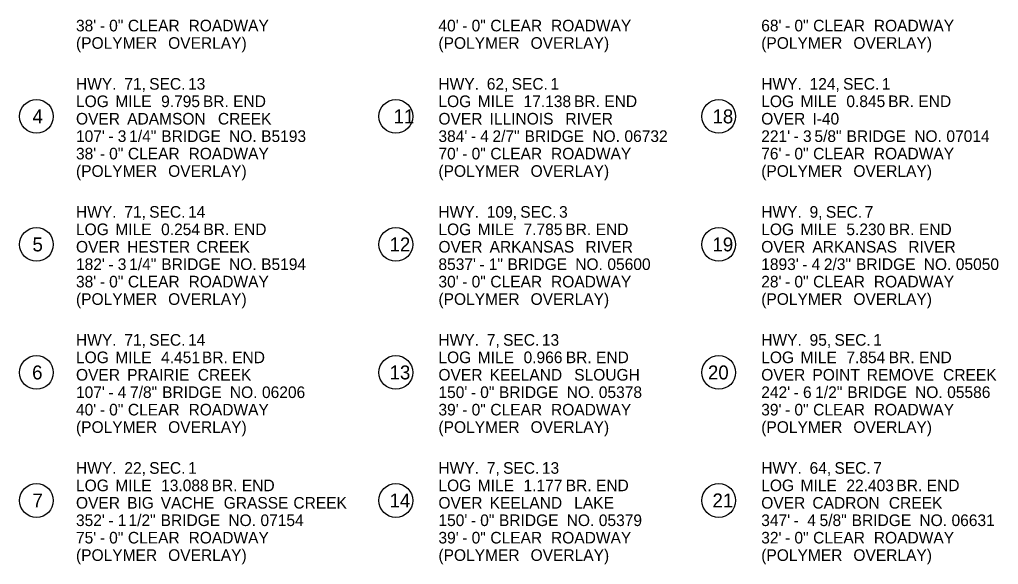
# Model space of a CAD drawing. Extents: x 1930546 to 1934225, y 596452 to 599553.
# Drawn here: x 1930658 to 1931501, y 598571 to 599039 of the extents above; entities that cross this region are included whole.
import ezdxf

# ---------------------------------------------------------------- set-up
doc = ezdxf.new("R2010")
doc.units = 0
doc.layers.add('Default', color=7, linetype='Continuous')
doc.layers.add('R_Border', color=7, linetype='Continuous')

msp = doc.modelspace()

# ---------------------------------------------------------------- linework, layer by layer
at = {"layer": 'R_Border'}
for centre in [(1930672.53, 598956.18), (1930981.88, 598956.18), (1931259.86, 598956.18), (1930672.53, 598846.01), (1930981.88, 598846.01), (1931259.86, 598846.01), (1930672.53, 598735.83), (1930981.88, 598735.83), (1931259.86, 598735.83), (1930672.53, 598625.66), (1930981.88, 598625.66), (1931259.86, 598625.66)]:
    msp.add_circle(centre, 14.52, dxfattribs=at)

# ---------------------------------------------------------------- texts
at = {"layer": 'Default'}
for s, p in [("38'", (1930706.56, 599029.34)), (' 0"', (1930731.4, 599029.34)), (' CLEAR', (1930747.53, 599029.34)), (' ROADWAY', (1930799.75, 599029.34)), ("40'", (1931018.56, 599029.34)), (' 0"', (1931043.4, 599029.34)), (' CLEAR', (1931059.53, 599029.34)), (' ROADWAY', (1931111.75, 599029.34)), ("68'", (1931296.43, 599029.34)), (' 0"', (1931321.28, 599029.34)), (' CLEAR', (1931337.41, 599029.34)), (' ROADWAY', (1931389.63, 599029.34)), (' -', (1930723.37, 599029.34)), (' -', (1931035.37, 599029.34)), (' -', (1931313.25, 599029.34)), ('(POLYMER', (1930706.56, 599014.34)), (' OVERLAY)', (1930782.17, 599014.34)), ('(POLYMER', (1931018.56, 599014.34)), (' OVERLAY)', (1931094.17, 599014.34)), ('(POLYMER', (1931296.43, 599014.34)), (' OVERLAY)', (1931372.04, 599014.34)), ('HWY.', (1930706.56, 598979.17)), (' 71,', (1930744.47, 598979.17)), (' SEC.', (1930765.87, 598979.17)), (' 13', (1930799.28, 598979.17)), ('HWY.', (1931018.56, 598979.17)), (' 62,', (1931056.47, 598979.17)), (' SEC.', (1931077.87, 598979.17)), (' 1', (1931111.28, 598979.17)), ('HWY.', (1931296.43, 598979.17)), (' 124,', (1931334.34, 598979.17)), (' SEC.', (1931363.14, 598979.17)), (' 1', (1931396.55, 598979.17)), ('LOG', (1930706.56, 598964.17)), (' MILE', (1930736.69, 598964.17)), (' 9.795', (1930776.13, 598964.17)), (' BR.', (1930812.09, 598964.17)), (' END', (1930838.12, 598964.17)), ('LOG', (1931018.56, 598964.17)), (' MILE', (1931048.69, 598964.17)), (' 17.138', (1931088.13, 598964.17)), (' BR.', (1931131.6, 598964.17)), (' END', (1931157.63, 598964.17)), ('LOG', (1931296.43, 598964.17)), (' MILE', (1931326.56, 598964.17)), (' 0.845', (1931366, 598964.17)), (' BR.', (1931401.96, 598964.17)), (' END', (1931427.99, 598964.17)), ('OVER', (1930706.56, 598949.17)), (' ADAMSON', (1930746.89, 598949.17)), (' CREEK', (1930825.02, 598949.17)), ('OVER', (1931018.56, 598949.17)), (' ILLINOIS', (1931058.89, 598949.17)), (' RIVER', (1931124.14, 598949.17)), ('OVER', (1931296.43, 598949.17)), (' I-40', (1931336.76, 598949.17)), ("107'", (1930706.56, 598934.17)), (' 3', (1930738.79, 598934.17)), (' 1/4"', (1930748.64, 598934.17)), (' BRIDGE', (1930776.26, 598934.17)), (' NO.', (1930834.58, 598934.17)), (' B5193', (1930862.24, 598934.17)), ("384'", (1931018.56, 598934.17)), (' 4', (1931050.79, 598934.17)), (' 2/7"', (1931061.36, 598934.17)), (' BRIDGE', (1931088.98, 598934.17)), (' NO.', (1931147.3, 598934.17)), (' 06732', (1931174.96, 598934.17)), ("221'", (1931296.43, 598934.17)), (' 3', (1931328.66, 598934.17)), (' 5/8"', (1931338.51, 598934.17)), (' BRIDGE', (1931366.14, 598934.17)), (' NO.', (1931424.45, 598934.17)), (' 07014', (1931452.11, 598934.17)), (' -', (1930730.76, 598934.17)), (' -', (1931042.76, 598934.17)), (' -', (1931320.64, 598934.17)), ("38'", (1930706.56, 598919.17)), (' 0"', (1930731.4, 598919.17)), (' CLEAR', (1930747.53, 598919.17)), (' ROADWAY', (1930799.75, 598919.17)), ("70'", (1931018.56, 598919.17)), (' 0"', (1931043.4, 598919.17)), (' CLEAR', (1931059.53, 598919.17)), (' ROADWAY', (1931111.75, 598919.17)), ("76'", (1931296.43, 598919.17)), (' 0"', (1931321.28, 598919.17)), (' CLEAR', (1931337.41, 598919.17)), (' ROADWAY', (1931389.63, 598919.17)), (' -', (1930723.37, 598919.17)), (' -', (1931035.37, 598919.17)), (' -', (1931313.25, 598919.17)), ('(POLYMER', (1930706.56, 598904.17)), (' OVERLAY)', (1930782.17, 598904.17)), ('(POLYMER', (1931018.56, 598904.17)), (' OVERLAY)', (1931094.17, 598904.17)), ('(POLYMER', (1931296.43, 598904.17)), (' OVERLAY)', (1931372.04, 598904.17)), ('HWY.', (1930706.56, 598868.99)), (' 71,', (1930744.47, 598868.99)), (' SEC.', (1930765.87, 598868.99)), (' 14', (1930799.28, 598868.99)), ('HWY.', (1931018.56, 598868.99)), (' 109,', (1931056.47, 598868.99)), (' SEC.', (1931085.26, 598868.99)), (' 3', (1931118.67, 598868.99)), ('HWY.', (1931296.43, 598868.99)), (' 9,', (1931334.34, 598868.99)), (' SEC.', (1931348.36, 598868.99)), (' 7', (1931381.77, 598868.99)), ('LOG', (1930706.56, 598853.99)), (' MILE', (1930736.69, 598853.99)), (' 0.254', (1930776.13, 598853.99)), (' BR.', (1930812.55, 598853.99)), (' END', (1930838.58, 598853.99)), ('LOG', (1931018.56, 598853.99)), (' MILE', (1931048.69, 598853.99)), (' 7.785', (1931088.13, 598853.99)), (' BR.', (1931124.09, 598853.99)), (' END', (1931150.12, 598853.99)), ('LOG', (1931296.43, 598853.99)), (' MILE', (1931326.56, 598853.99)), (' 5.230', (1931366, 598853.99)), (' BR.', (1931402.41, 598853.99)), (' END', (1931428.44, 598853.99)), ('OVER', (1930706.56, 598838.99)), (' HESTER', (1930746.89, 598838.99)), (' CREEK', (1930806.49, 598838.99)), ('OVER', (1931018.56, 598838.99)), (' ARKANSAS', (1931058.89, 598838.99)), (' RIVER', (1931141.39, 598838.99)), ('OVER', (1931296.43, 598838.99)), (' ARKANSAS', (1931336.76, 598838.99)), (' RIVER', (1931419.26, 598838.99)), (' 1/4"', (1930748.64, 598823.99)), (' 2/3"', (1931346.62, 598823.99)), ("182'", (1930706.56, 598823.99)), (' -', (1930730.76, 598823.99)), (' 3', (1930738.79, 598823.99)), (' BRIDGE', (1930776.26, 598823.99)), (' NO.', (1930834.58, 598823.99)), (' B5194', (1930862.24, 598823.99)), ("8537'", (1931018.56, 598823.99)), (' -', (1931050.15, 598823.99)), (' 1"', (1931058.18, 598823.99)), (' BRIDGE', (1931074.31, 598823.99)), (' NO.', (1931132.63, 598823.99)), (' 05600', (1931160.29, 598823.99)), ("1893'", (1931296.43, 598823.99)), (' -', (1931328.02, 598823.99)), (' 4', (1931336.05, 598823.99)), (' BRIDGE', (1931374.25, 598823.99)), (' NO.', (1931432.56, 598823.99)), (' 05050', (1931460.22, 598823.99)), ("38'", (1930706.56, 598808.99)), (' 0"', (1930731.4, 598808.99)), (' CLEAR', (1930747.53, 598808.99)), (' ROADWAY', (1930799.75, 598808.99)), ("30'", (1931018.56, 598808.99)), (' 0"', (1931043.4, 598808.99)), (' CLEAR', (1931059.53, 598808.99)), (' ROADWAY', (1931111.75, 598808.99)), ("28'", (1931296.43, 598808.99)), (' 0"', (1931321.28, 598808.99)), (' CLEAR', (1931337.41, 598808.99)), (' ROADWAY', (1931389.63, 598808.99)), (' -', (1930723.37, 598808.99)), (' -', (1931035.37, 598808.99)), (' -', (1931313.25, 598808.99)), ('(POLYMER', (1930706.56, 598793.99)), (' OVERLAY)', (1930782.17, 598793.99)), ('(POLYMER', (1931018.56, 598793.99)), (' OVERLAY)', (1931094.17, 598793.99)), ('(POLYMER', (1931296.43, 598793.99)), (' OVERLAY)', (1931372.04, 598793.99)), ('HWY.', (1930706.56, 598758.82)), (' 71,', (1930744.47, 598758.82)), (' SEC.', (1930765.87, 598758.82)), (' 14', (1930799.28, 598758.82)), ('HWY.', (1931018.56, 598758.82)), (' 7,', (1931056.47, 598758.82)), (' SEC.', (1931070.48, 598758.82)), (' 13', (1931103.9, 598758.82)), ('HWY.', (1931296.43, 598758.82)), (' 95,', (1931334.34, 598758.82)), (' SEC.', (1931355.75, 598758.82)), (' 1', (1931389.16, 598758.82)), ('LOG', (1930706.56, 598743.82)), (' MILE', (1930736.69, 598743.82)), (' 4.451', (1930776.13, 598743.82)), (' BR.', (1930811.25, 598743.82)), (' END', (1930837.28, 598743.82)), ('LOG', (1931018.56, 598743.82)), (' MILE', (1931048.69, 598743.82)), (' 0.966', (1931088.13, 598743.82)), (' BR.', (1931124.49, 598743.82)), (' END', (1931150.52, 598743.82)), ('LOG', (1931296.43, 598743.82)), (' MILE', (1931326.56, 598743.82)), (' 7.854', (1931366, 598743.82)), (' BR.', (1931402.43, 598743.82)), (' END', (1931428.46, 598743.82)), ('OVER', (1930706.56, 598728.82)), (' PRAIRIE', (1930746.89, 598728.82)), (' CREEK', (1930807.67, 598728.82)), ('OVER', (1931018.56, 598728.82)), (' KEELAND', (1931058.89, 598728.82)), (' SLOUGH', (1931131.72, 598728.82)), ('OVER', (1931296.43, 598728.82)), (' POINT', (1931336.76, 598728.82)), (' REMOVE', (1931383.55, 598728.82)), (' CREEK', (1931449.25, 598728.82)), ("107'", (1930706.56, 598713.82)), (' -', (1930730.76, 598713.82)), (' 4', (1930738.79, 598713.82)), (' 7/8"', (1930749.36, 598713.82)), (' BRIDGE', (1930776.98, 598713.82)), (' NO.', (1930835.3, 598713.82)), (' 06206', (1930862.96, 598713.82)), ("150'", (1931018.56, 598713.82)), (' -', (1931042.76, 598713.82)), (' 0"', (1931050.79, 598713.82)), (' BRIDGE', (1931066.92, 598713.82)), (' NO.', (1931125.24, 598713.82)), (' 05378', (1931152.9, 598713.82)), ("242'", (1931296.43, 598713.82)), (' -', (1931320.64, 598713.82)), (' 6', (1931328.66, 598713.82)), (' 1/2"', (1931339.17, 598713.82)), (' BRIDGE', (1931366.8, 598713.82)), (' NO.', (1931425.12, 598713.82)), (' 05586', (1931452.78, 598713.82)), ("40'", (1930706.56, 598698.82)), (' 0"', (1930731.4, 598698.82)), (' CLEAR', (1930747.53, 598698.82)), (' ROADWAY', (1930799.75, 598698.82)), ("39'", (1931018.56, 598698.82)), (' 0"', (1931043.4, 598698.82)), (' CLEAR', (1931059.53, 598698.82)), (' ROADWAY', (1931111.75, 598698.82)), ("39'", (1931296.43, 598698.82)), (' 0"', (1931321.28, 598698.82)), (' CLEAR', (1931337.41, 598698.82)), (' ROADWAY', (1931389.63, 598698.82)), (' -', (1930723.37, 598698.82)), (' -', (1931035.37, 598698.82)), (' -', (1931313.25, 598698.82)), ('(POLYMER', (1930706.56, 598683.82)), (' OVERLAY)', (1930782.17, 598683.82)), ('(POLYMER', (1931018.56, 598683.82)), (' OVERLAY)', (1931094.17, 598683.82)), ('(POLYMER', (1931296.43, 598683.82)), (' OVERLAY)', (1931372.04, 598683.82)), ('HWY.', (1930706.56, 598648.64)), (' 22,', (1930744.47, 598648.64)), (' SEC.', (1930765.87, 598648.64)), (' 1', (1930799.28, 598648.64)), ('HWY.', (1931018.56, 598648.64)), (' 7,', (1931056.47, 598648.64)), (' SEC.', (1931070.48, 598648.64)), (' 13', (1931103.9, 598648.64)), ('HWY.', (1931296.43, 598648.64)), (' 64,', (1931334.34, 598648.64)), (' SEC.', (1931355.75, 598648.64)), (' 7', (1931389.16, 598648.64)), ('LOG', (1930706.56, 598633.64)), (' MILE', (1930736.69, 598633.64)), (' 13.088', (1930776.13, 598633.64)), (' BR.', (1930819.6, 598633.64)), (' END', (1930845.63, 598633.64)), ('LOG', (1931018.56, 598633.64)), (' MILE', (1931048.69, 598633.64)), (' 1.177', (1931088.13, 598633.64)), (' BR.', (1931124.4, 598633.64)), (' END', (1931150.43, 598633.64)), ('LOG', (1931296.43, 598633.64)), (' MILE', (1931326.56, 598633.64)), (' 22.403', (1931366, 598633.64)), (' BR.', (1931409.09, 598633.64)), (' END', (1931435.13, 598633.64)), ('OVER', (1930706.56, 598618.64)), (' BIG', (1930746.89, 598618.64)), (' VACHE', (1930775.79, 598618.64)), (' GRASSE', (1930830, 598618.64)), (' CREEK', (1930889.97, 598618.64)), ('OVER', (1931018.56, 598618.64)), (' KEELAND', (1931058.89, 598618.64)), (' LAKE', (1931131.72, 598618.64)), ('OVER', (1931296.43, 598618.64)), (' CADRON', (1931336.76, 598618.64)), (' CREEK', (1931402.59, 598618.64)), ("352'", (1930706.56, 598603.64)), (' -', (1930730.76, 598603.64)), (' 1', (1930738.79, 598603.64)), (' 1/2"', (1930748.05, 598603.64)), (' BRIDGE', (1930775.68, 598603.64)), (' NO.', (1930834, 598603.64)), (' 07154', (1930861.66, 598603.64)), ("150'", (1931018.56, 598603.64)), (' -', (1931042.76, 598603.64)), (' 0"', (1931050.79, 598603.64)), (' BRIDGE', (1931066.92, 598603.64)), (' NO.', (1931125.24, 598603.64)), (' 05379', (1931152.9, 598603.64)), ("347'", (1931296.43, 598603.64)), (' -', (1931320.64, 598603.64)), ('  4', (1931328.66, 598603.64)), (' 5/8"', (1931342.92, 598603.64)), (' BRIDGE', (1931370.55, 598603.64)), (' NO.', (1931428.86, 598603.64)), (' 06631', (1931456.52, 598603.64)), ("75'", (1930706.56, 598588.64)), (' 0"', (1930731.4, 598588.64)), (' CLEAR', (1930747.53, 598588.64)), (' ROADWAY', (1930799.75, 598588.64)), ("39'", (1931018.56, 598588.64)), (' 0"', (1931043.4, 598588.64)), (' CLEAR', (1931059.53, 598588.64)), (' ROADWAY', (1931111.75, 598588.64)), ("32'", (1931296.43, 598588.64)), (' 0"', (1931321.28, 598588.64)), (' CLEAR', (1931337.41, 598588.64)), (' ROADWAY', (1931389.63, 598588.64)), (' -', (1930723.37, 598588.64)), (' -', (1931035.37, 598588.64)), (' -', (1931313.25, 598588.64)), ('(POLYMER', (1930706.56, 598573.64)), (' OVERLAY)', (1930782.17, 598573.64)), ('(POLYMER', (1931018.56, 598573.64)), (' OVERLAY)', (1931094.17, 598573.64)), ('(POLYMER', (1931296.43, 598573.64)), (' OVERLAY)', (1931372.04, 598573.64))]:
    msp.add_text(s, height=10, dxfattribs=at).set_placement(p)
at = {"layer": 'R_Border'}
for s, p in [('4', (1930669.12, 598950.18)), ('11', (1930979.9, 598950.18)), ('18', (1931254.48, 598950.18)), ('5', (1930669.12, 598840.01)), ('12', (1930976.5, 598840.01)), ('19', (1931254.43, 598840.01)), ('6', (1930668.79, 598729.83)), ('13', (1930976.5, 598729.83)), ('20', (1931250.56, 598729.83)), ('7', (1930669.12, 598619.66)), ('14', (1930976.5, 598619.66)), ('21', (1931254.48, 598619.66))]:
    msp.add_text(s, height=12, rotation=360, dxfattribs=at).set_placement(p)

doc.saveas('drawing.dxf')
